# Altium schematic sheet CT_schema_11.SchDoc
size 274 x 160 mm
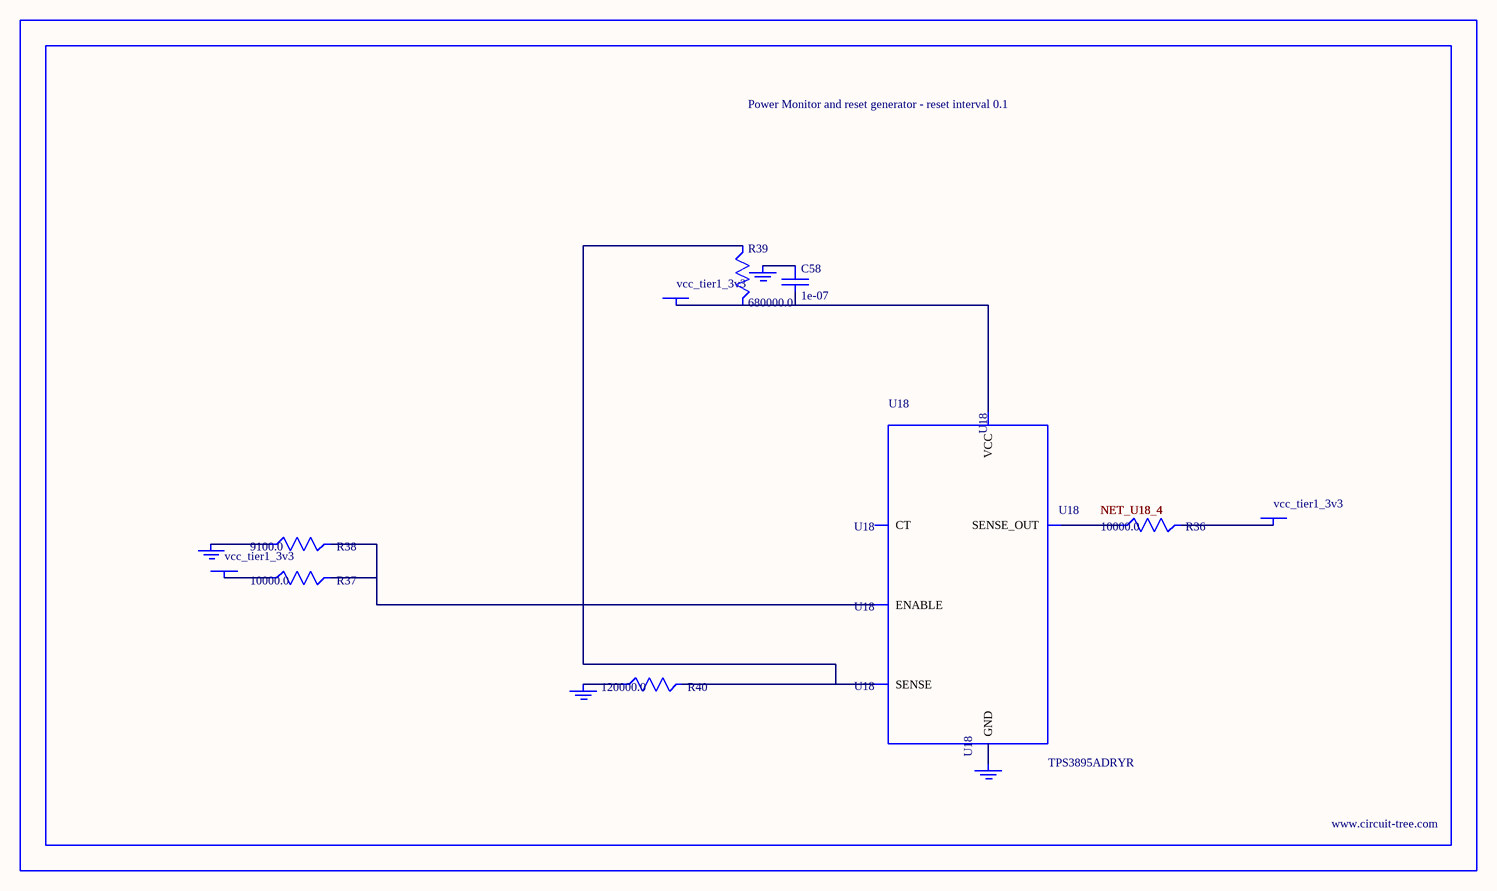
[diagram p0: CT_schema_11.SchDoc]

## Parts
BORDER10  (no value)
C58  1e-07  [C0402]
GND_INSTANCE_10_0  (no value)
GND_INSTANCE_10_1  (no value)
GND_INSTANCE_10_2  (no value)
GND_INSTANCE_10_3  (no value)
POWER_INSTANCE_10_0  vcc_tier1_3v3
POWER_INSTANCE_10_1  vcc_tier1_3v3
POWER_INSTANCE_10_2  vcc_tier1_3v3
R36  10000.0  [R0603]
R37  10000.0  [R0603]
R38  9100.0  [R0603]
R39  680000.0  [R0603]
R40  120000.0  [R0603]
U18  TPS3895ADRYR  [SON-6]

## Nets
NetC58_1: C58.1 GND_INSTANCE_10_2.0(GND)
NetC58_2: C58.2 POWER_INSTANCE_10_2.0(PWR) R39.2 U18.6(VCC)
NetGND_INSTANCE_10_0_0: GND_INSTANCE_10_0.0(GND) R38.1
NetGND_INSTANCE_10_1_0: GND_INSTANCE_10_1.0(GND) R40.1
NetGND_INSTANCE_10_3_0: GND_INSTANCE_10_3.0(GND) U18.2(GND)
NetPOWER_INSTANCE_10_0_0: POWER_INSTANCE_10_0.0(PWR) R37.1
NetPOWER_INSTANCE_10_1_0: POWER_INSTANCE_10_1.0(PWR) R36.2
NetR36_1: R36.1 U18.4(SENSE_OUT)
NetR37_2: R37.2 R38.2 U18.1(ENABLE)
NetR39_1: R39.1 R40.2 U18.3(SENSE)

Not connected (* = marked no-connect by the designer): U18 5(CT)

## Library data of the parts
BORDER10 = BORDER_PAGE10
C58 = C0402C104K3RACTU
GND_INSTANCE_10_0-GND_INSTANCE_10_3 = GND
POWER_INSTANCE_10_0-POWER_INSTANCE_10_2 = PWR
R36 R37 = RC0603JR-0710KL
R38 = RC0603JR-079K1L
R39 = RC0603JR-07680KL
R40 = RC0603JR-07120KL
